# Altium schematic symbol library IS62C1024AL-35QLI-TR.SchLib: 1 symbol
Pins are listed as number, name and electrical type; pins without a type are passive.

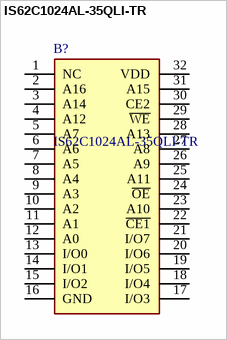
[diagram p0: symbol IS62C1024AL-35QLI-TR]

## IS62C1024AL-35QLI-TR
designator B?
SRAM 1Mb 128K x 8 35ns 5v Async SRAM 5v; Manufacturer_Name: Integrated Silicon Solution Inc.; Geometry.Height: 3.05mm
footprint SOIC127P1412X305-32N
pins: 1 NC, 2 A16, 3 A14, 4 A12, 5 A7, 6 A6, 7 A5, 8 A4, 9 A3, 10 A2, 11 A1, 12 A0, 13 I/O0, 14 I/O1, 15 I/O2, 16 GND, 17 I/O3, 18 I/O4, 19 I/O5, 20 I/O6, 21 I/O7, 22 ~{CE1}, 23 A10, 24 ~{OE}, 25 A11, 26 A9, 27 A8, 28 A13, 29 ~{WE}, 30 CE2, 31 A15, 32 VDD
